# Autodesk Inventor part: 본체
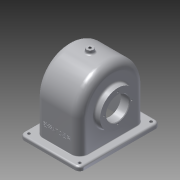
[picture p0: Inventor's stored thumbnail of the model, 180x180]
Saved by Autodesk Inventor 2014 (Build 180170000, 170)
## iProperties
Created: 2016-01
Part Number: 본체
Material: 알루미늄 6061
Document SubType Name: Modeling
Designer: USER
Density: 2.71 g/cm^3
Appearance: 알루미늄 - 평지
Mass: 809.582 g
Surface Area: 1000.47 cm^2
Volume: 298.739 cm^3
Author: USER
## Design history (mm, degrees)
sketch "스케치1"
  geometry: L1 (-57, 0)-(-57, -57); L2 (-57, -57)-(57, -57); L3 (57, 0)-(57, -57); A1 r 57 centre (0, 0) between (57, 0) and (-57, 0); 1 further point
  constraints: 6 end point, 2 perpendicular, 2 point on circle, 2 tangent, 1 centre point, 1 coincident, 1 vertical
  dimensions: "d0" = 114 diameter of A1; "d1" = 57 distance of L1.start L1.end
extrude "돌출1" new body sketch "스케치1" stored distance "d2" = 77; taper "d3" = 0 deg
feature "쉘1" dims "d4" = 6
sketch "스케치3"
  geometry: L1 (0, -51)-(-57, -51) reference; L2 (-57, 51)-(0, 51) reference; L3 (-57, -51)-(-57, 51) reference; A1 r 51 centre (0, 0) between (0, -51) and (0, 51) reference
extrude "돌출2" cut sketch "스케치3" distance "d5" = 1; taper "d6" = 0 deg
sketch "스케치4"
  geometry: L1 (57, -51)-(0, -51) reference; L2 (57, 51)-(57, -51) reference; L3 (0, 51)-(57, 51) reference; A1 r 51 centre (0, 0) between (0, 51) and (0, -51) reference
extrude "돌출3" cut sketch "스케치4" distance "d7" = 1; taper "d8" = 0 deg
sketch "스케치6"
  geometry: L1 (72, -108)-(5, -108) reference; L2 (5, -108)-(5, -6) reference; L3 (5, -6)-(72, -6) reference; L4 (72, -6)-(72, -108) reference; L5 (-13.5, 13)-(90.5, 13); L6 (90.5, 13)-(90.5, -127); L7 (90.5, -127)-(-13.5, -127); L8 (-13.5, -127)-(-13.5, 13); 3 further points
  constraints: 8 end point, 2 midpoint, 2 parallel, 1 horizontal, 1 horizontal alignment, 1 perpendicular, 1 vertical alignment
  dimensions: "d10" = 104 distance between parallel lines of L6 L8; "d11" = 140 distance between parallel lines of L7 L5
extrude "돌출4" join sketch "스케치6" distance "d12" = 7; taper "d13" = 0 deg
sketch "스케치7"
  geometry: C1 r 2.5 at (-5.5, 5); C2 r 2.5 at (82.5, 5); C3 r 2.5 at (-5.5, -119); C4 r 2.5 at (82.5, -119); 1 further point
  constraints: 4 centre point, 2 horizontal alignment, 2 vertical alignment
  dimensions: "d14" = 5 diameter of C1; "d15" = 5 diameter of C2; "d16" = 5 diameter of C3; "d17" = 5 diameter of C4; "d20" = 44 horizontal distance of C2.centre point (38.5, -57); "d21" = 62 vertical distance of point (38.5, -57) C2.centre; "d22" = 124 distance of C4.centre C2.centre; "d23" = 88 distance of C1.centre C2.centre
extrude "돌출5" cut sketch "스케치7" distance "d24" = 7; taper "d25" = 0 deg
fillet "모깎기1" dims "d26" = 14
fillet "모깎기2" dims "d27" = 9
fillet "모깎기3" dims "d28" = 8
node "작업 평면1"
sketch "스케치8"
  geometry: C1 r 6 at (38.5, -57); 1 further point
  constraints: 1 centre point, 1 coincident
  dimensions: "d30" = 12 diameter of C1
extrude "돌출6" join sketch "스케치8" stored distance "d31" = 7; taper "d32" = 0 deg
sketch "스케치9"
  geometry: C1 r 6 at (0, 0) reference; 1 further point
  constraints: 1 coincident
hole "구멍1" sketch "스케치9" at (0, 0) diameter "d33" = 4.459; stored, may be unused: countersink angle "d37" = 90 deg, drill point angle "d39" = 118 deg; dims "d34" = 20, "d35" = 4, "d36" = 2, "d38" = 8
fillet "모깎기4" dims "d40" = 3
sketch "스케치10"
  geometry: L1 (64, 62)-(64, -62) reference; C1 r 31 at (4, 0); A1 r 43 centre (0, 0) between (0, 43) and (0, -43) reference
  constraints: 1 centre point, 1 horizontal alignment
  dimensions: "d41" = 62 diameter of C1; "d42" = 60 distance from line of C1.centre L1
extrude "돌출7" join sketch "스케치10" distance "d43" = 10; taper "d44" = 0 deg
sketch "스케치11"
  geometry: C1 r 31 at (0, 0) reference; C2 r 20 at (0, 0); 1 further point
  constraints: 1 centre point, 1 coincident
  dimensions: "d45" = 40 diameter of C2
extrude "돌출8" cut sketch "스케치11" distance "d46" = 15; taper "d47" = 0 deg
sketch "스케치12"
  geometry: C1 r 20 at (0, 0) reference; 2 further points
  constraints: 1 horizontal alignment
  dimensions: "d48" = 24 distance of C1.centre point (-24, 0)
hole "구멍2" sketch "스케치12" at (-24, 0) diameter "d49" = 2.459; stored, may be unused: countersink angle "d53" = 90 deg, drill point angle "d55" = 118 deg; dims "d50" = 6, "d51" = 4, "d52" = 2, "d54" = 8
node "작업 평면2"
sketch "스케치13"
  geometry: L1 (-64, -42)-(-64, 42) reference; C1 r 28 at (-4, 0); 1 further point
  constraints: 1 centre point, 1 horizontal alignment
  dimensions: "d60" = 56 diameter of C1; "d61" = 60 distance from line of C1.centre L1
extrude "돌출9" join sketch "스케치13" stored distance "d62" = 15; taper "d63" = 40 deg
sketch "스케치15"
  geometry: C1 r 28 at (0, 0) reference; C2 r 20 at (0, 0); 1 further point
  constraints: 1 centre point, 1 coincident
  dimensions: "d64" = 40 diameter of C2
extrude "돌출10" cut sketch "스케치15" distance "d65" = 16; taper "d66" = 0 deg
sketch "스케치16"
  geometry: L1 (38.5, 43)-(38.5, 0) reference; L2 (19.5, 24)-(33.5, 35.747) reference; L3 (35.5, 30.899)-(38.5, 33.416); L4 (35.5, 30.899)-(35.5, -4); L5 (38.5, 33.416)-(38.5, 0); L6 (0, -4)-(66.066, -4); L7 (46.5, -64)-(41.5, -64) reference; L8 (38.5, 0)-(38.5, -57) reference; L9 (35.5, -4)-(38.5, -4); 1 further point
  constraints: 10 end point, 4 point on line, 1 collinear, 1 parallel
  dimensions: "d67" = 5 distance between parallel lines of L2 L3; "d68" = 3 distance between parallel lines of L1 L4; "d69" = 60 distance between parallel lines of L6 L7
revolve "회전1" sketch "스케치16" stored, may be unused: angle "d70" = 90 deg
sketch "스케치17"
  geometry: C1 r 20 at (0, 0) reference; 2 further points
  constraints: 1 vertical alignment
  dimensions: "d71" = 28 distance of C1.centre point (0, 28)
hole "구멍3" sketch "스케치17" at (0, 28) diameter "d72" = 2.459; stored, may be unused: countersink angle "d76" = 90 deg, drill point angle "d78" = 118 deg; dims "d73" = 7, "d74" = 4, "d75" = 2, "d77" = 9
sketch "스케치18"
  geometry: L1 (-14, 0)-(-14, -57) reference; L2 (68.5, -64)-(-19.5, -64) reference; 2 further points
  constraints: 1 other
  dimensions: "d82" = 38.5 distance from line of point (24.5, -34) L1; "d83" = 30 distance from line of L2 point (24.5, -34)
extrude "돌출11" join sketch "스케치18" distance "d84" = 0.5; taper "d85" = 0 deg
fillet "모깎기5" dims "d86" = 3
fillet "모깎기6" dims "d87" = 1
chamfer "모따기1" distance "d88" = 1; stored, may be unused: second distance "d89" = 2, angle "d90" = 45 deg
fillet "모깎기7" dims "d91" = 3
node "솔리드1"
pattern_circular "원형 패턴1" dims angle "d57" = 360 deg
pattern_circular "원형 패턴2" dims angle "d80" = 360 deg
other parameters: "d29" = -127, "d59" = -19
